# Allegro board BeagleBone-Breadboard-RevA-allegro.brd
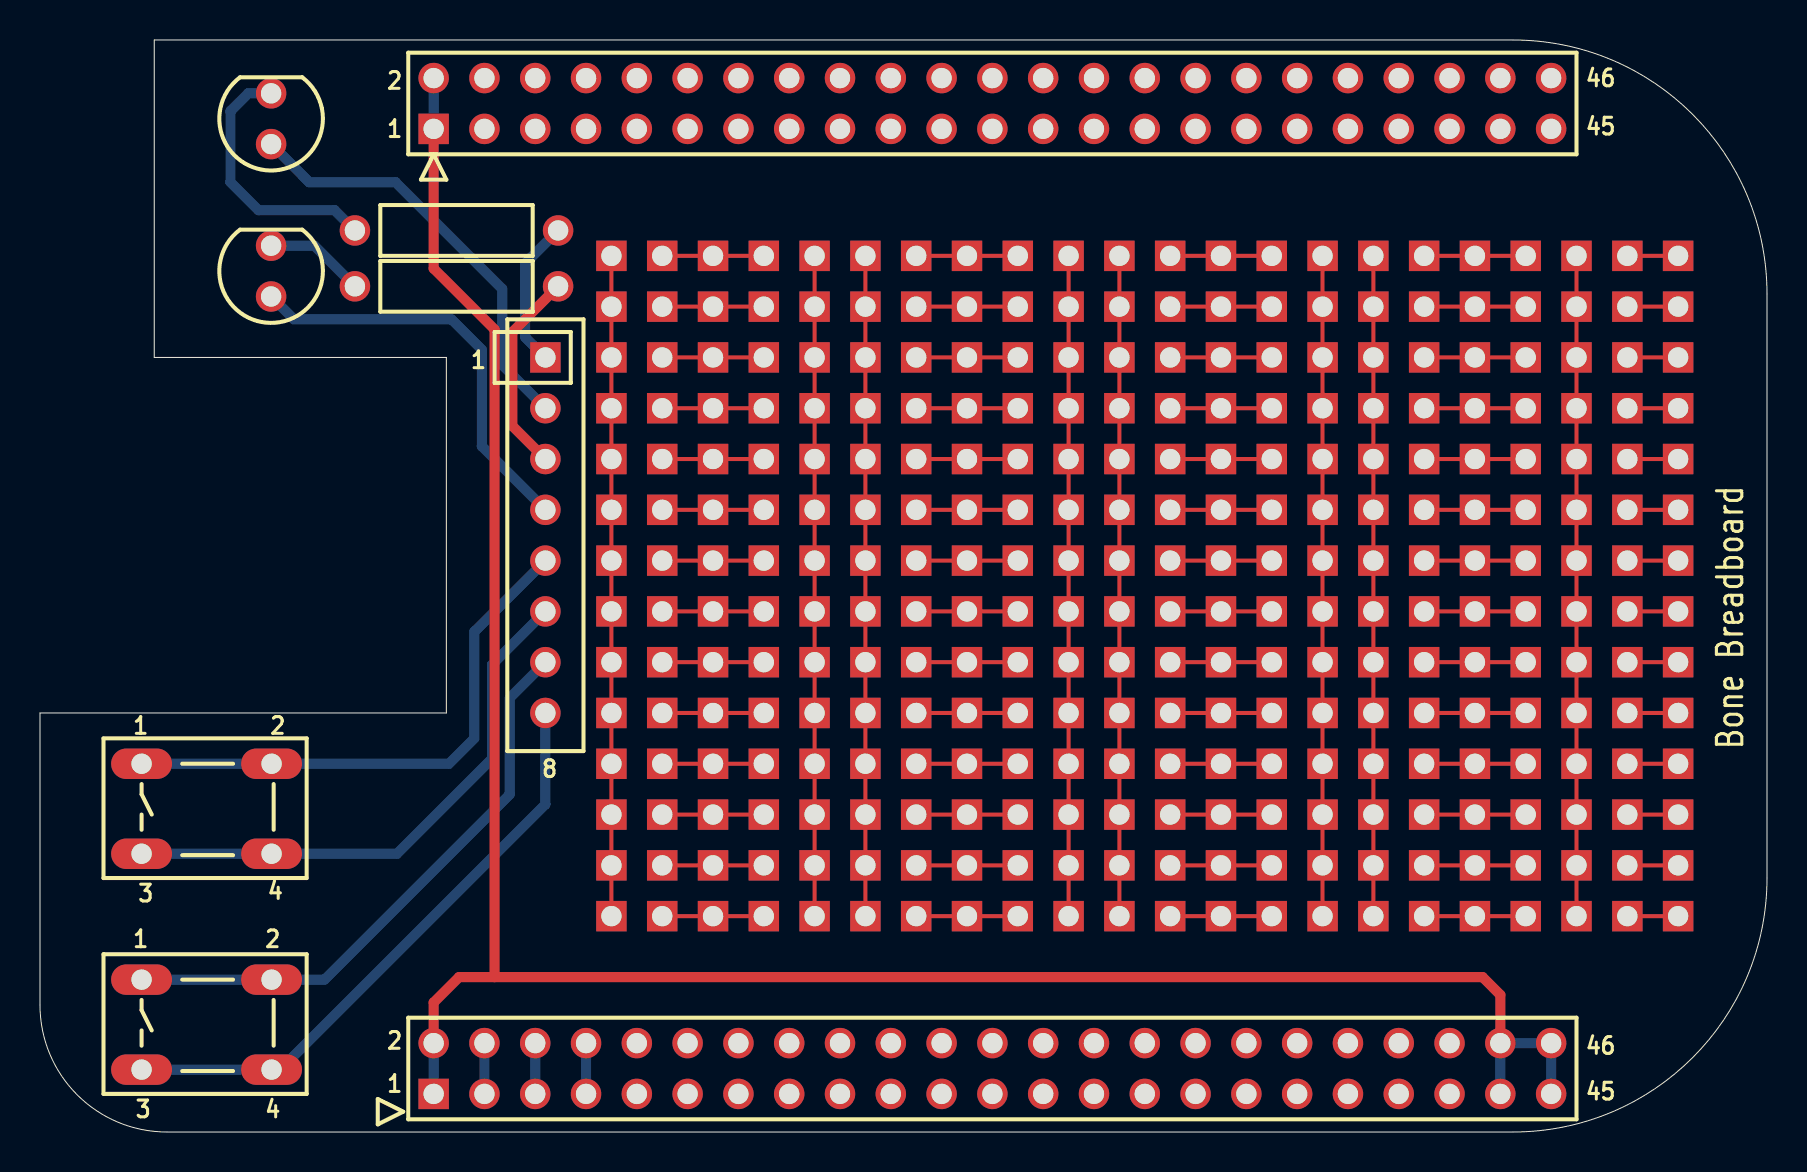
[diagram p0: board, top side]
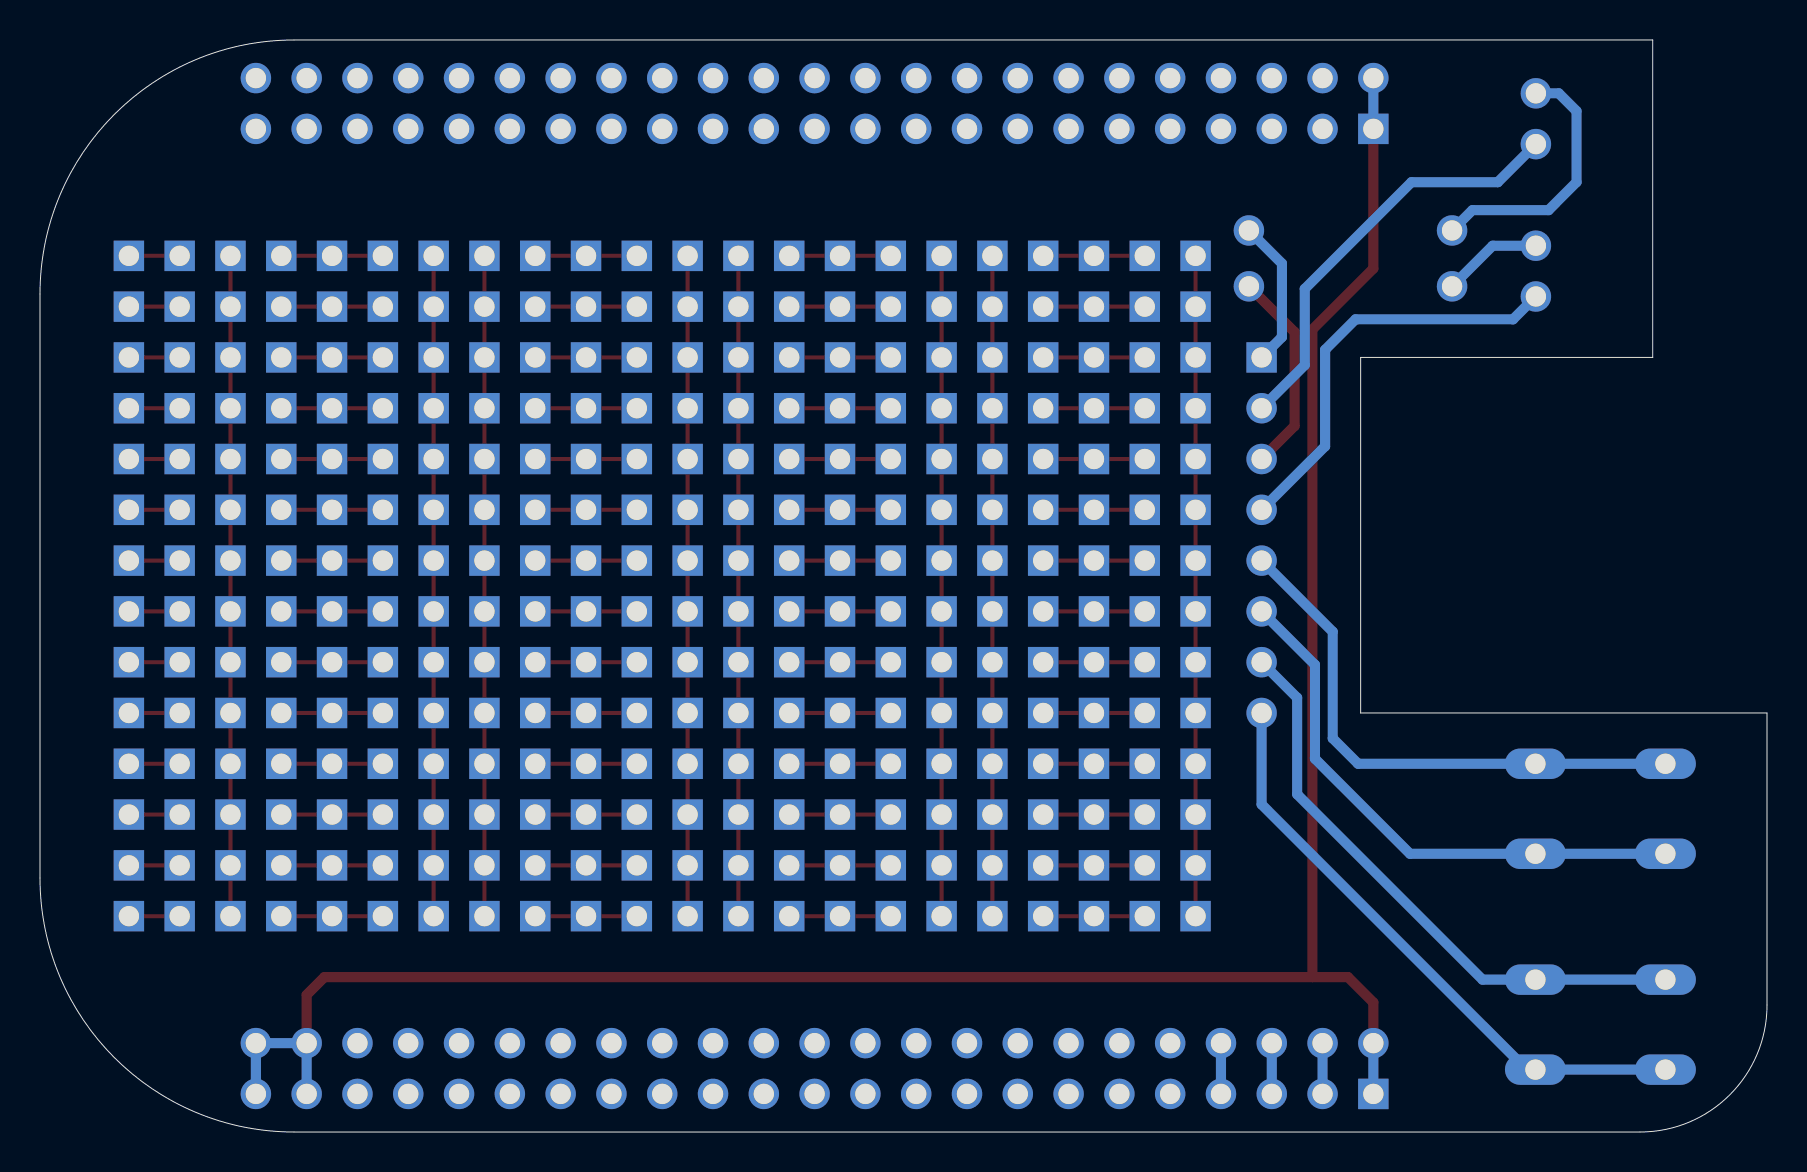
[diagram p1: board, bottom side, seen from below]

Outline 86.36 x 54.61 mm; copper layers: TOP, BOTTOM. Coordinates in mm from the lower left corner of the outline.

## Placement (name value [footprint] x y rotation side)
D1  LED  [LEDS]  11.56 50.67 90 top
D2  LED  [LEDS]  11.56 43.05 90 top
NOREF  -  []  0 0 0 top
NOREF#2  -  []  -358.14 -231.14 0 top
P1  FEMALE HEADER 2x23  [2X23_HDR_FEMALE]  19.68 50.16 180 top
P2  FEMALE HEADER 2x23  [2X23_HDR_FEMALE]  19.68 1.91 180 top
P3  8-PIN HEADER  [8_PIN_HDR_FEMALE]  25.27 38.73 90 top
R1  470  [RESISTOR]  20.83 45.09 180 top
R2  470  [RESISTOR]  20.83 42.29 180 top
S1  SW DIP-2  [BUTTONS]  5.08 18.41 0 top
S2  SW DIP-2  [BUTTONS]  5.08 7.62 0 top
TH1  CONN SOCKET 14x2  [2X14HEADER]  33.66 27.3 0 top
TH2  CONN SOCKET 14x2  [2X14HEADER]  46.35 27.3 0 top
TH3  CONN SOCKET 14x2  [2X14HEADER]  59.05 27.3 0 top
TH4  CONN SOCKET 14x2  [2X14HEADER]  71.75 27.3 0 top
TH5  CONN SOCKET 21x2  [3X14HEADER]  33.66 27.3 0 top
TH6  CONN SOCKET 21x2  [3X14HEADER]  46.35 27.3 0 top
TH7  CONN SOCKET 21x2  [3X14HEADER]  59.05 27.3 0 top
TH8  CONN SOCKET 21x2  [3X14HEADER]  71.75 27.3 0 top
TH9  CONN SOCKET 14  [14HEADER]  79.38 27.3 0 top
TH10  CONN SOCKET 14  [14HEADER]  81.92 27.3 0 top

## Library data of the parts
D1 D2 = LED
P1 P2 = FEMALE HEADER 2x23
P3 = 8-PIN HEADER
R1 R2 = R
S1 S2 = SW DIP-2
TH1-TH4 = CONN SOCKET 14x2
TH5-TH8 = CONN SOCKET 21x2
TH9 TH10 = CONN SOCKET 14

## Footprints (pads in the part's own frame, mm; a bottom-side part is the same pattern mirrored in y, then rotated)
2X14HEADER
  rect 1.524x1.524 hole 1.016: 1(-5.08,16.51) 2(5.08,16.51) 3(-5.08,13.97) 4(5.08,13.97) 5(-5.08,11.43) 6(5.08,11.43) 7(-5.08,8.89) 8(5.08,8.89) 9(-5.08,6.35) 10(5.08,6.35) 11(-5.08,3.81) 12(5.08,3.81) 13(-5.08,1.27) 14(5.08,1.27) 15(-5.08,-1.27) 16(5.08,-1.27) 17(-5.08,-3.81) 18(5.08,-3.81) 19(-5.08,-6.35) 20(5.08,-6.35) 21(-5.08,-8.89) 22(5.08,-8.89) 23(-5.08,-11.43) 24(5.08,-11.43) 25(-5.08,-13.97) 26(5.08,-13.97) 27(-5.08,-16.51) 28(5.08,-16.51)
2X23_HDR_FEMALE
  rect 1.524x1.524 hole 1.016: 1(0,0)
  round 1.524 hole 1.016: 2(0,-2.54) 3(-2.54,0) 4(-2.54,-2.54) 5(-5.08,0) 6(-5.08,-2.54) 7(-7.62,0) 8(-7.62,-2.54) 9(-10.16,0) 10(-10.16,-2.54) 11(-12.7,0) 12(-12.7,-2.54) 13(-15.24,0) 14(-15.24,-2.54) 15(-17.78,0) 16(-17.78,-2.54) 17(-20.32,0) 18(-20.32,-2.54) 19(-22.86,0) 20(-22.86,-2.54) 21(-25.4,0) 22(-25.4,-2.54) 23(-27.94,0) 24(-27.94,-2.54) 25(-30.48,0) 26(-30.48,-2.54) 27(-33.02,0) 28(-33.02,-2.54) 29(-35.56,0) 30(-35.56,-2.54) 31(-38.1,0) 32(-38.1,-2.54) 33(-40.64,0) 34(-40.64,-2.54) 35(-43.18,0) 36(-43.18,-2.54) 37(-45.72,0) 38(-45.72,-2.54) 39(-48.26,0) 40(-48.26,-2.54) 41(-50.8,0) 42(-50.8,-2.54) 43(-53.34,0) 44(-53.34,-2.54) 45(-55.88,0) 46(-55.88,-2.54)
3X14HEADER
  rect 1.524x1.524 hole 1.016: 1(-2.54,16.51) 2(0,16.51) 3(2.54,16.51) 4(-2.54,13.97) 5(0,13.97) 6(2.54,13.97) 7(-2.54,11.43) 8(0,11.43) 9(2.54,11.43) 10(-2.54,8.89) 11(0,8.89) 12(2.54,8.89) 13(-2.54,6.35) 14(0,6.35) 15(2.54,6.35) 16(-2.54,3.81) 17(0,3.81) 18(2.54,3.81) 19(-2.54,1.27) 20(0,1.27) 21(2.54,1.27) 22(-2.54,-1.27) 23(0,-1.27) 24(2.54,-1.27) 25(-2.54,-3.81) 26(0,-3.81) 27(2.54,-3.81) 28(-2.54,-6.35) 29(0,-6.35) 30(2.54,-6.35) 31(-2.54,-8.89) 32(0,-8.89) 33(2.54,-8.89) 34(-2.54,-11.43) 35(0,-11.43) 36(2.54,-11.43) 37(-2.54,-13.97) 38(0,-13.97) 39(2.54,-13.97) 40(-2.54,-16.51) 41(0,-16.51) 42(2.54,-16.51)
8_PIN_HDR_FEMALE
  rect 1.524x1.524 hole 1.016: 1(0,0)
  round 1.524 hole 1.016: 2(-2.54,0) 3(-5.08,0) 4(-7.62,0) 5(-10.16,0) 6(-12.7,0) 7(-15.24,0) 8(-17.78,0)
14HEADER
  rect 1.524x1.524 hole 1.016: 1(0,16.51) 2(0,13.97) 3(0,11.43) 4(0,8.89) 5(0,6.35) 6(0,3.81) 7(0,1.27) 8(0,-1.27) 9(0,-3.81) 10(0,-6.35) 11(0,-8.89) 12(0,-11.43) 13(0,-13.97) 14(0,-16.51)
BUTTONS
  oval 3.048x1.524 hole 1.016: 1(0,0) 2(6.5,0) 3(0,-4.5) 4(6.5,-4.5)
LEDS
  round 1.524 hole 1.016: 1(-1.27,0) 2(1.27,0)
RESISTOR
  round 1.524 hole 1.016: 1(-5.08,0) 2(5.08,0)

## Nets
AGND: P2.34
DGND: P1.1 P1.2 P2.1 P2.2 P2.43 P2.44 P2.45 P2.46
VDD_3V3EXP: P2.3 P2.4
VDD_5V: P2.5 P2.6
VDD_ADC: P2.32
AIN0: P2.39
AIN1: P2.40
AIN2: P2.37
AIN3: P2.38
AIN4: P2.33
AIN5: P2.36
AIN6: P2.35
CLKOUT2: P2.41
EHRPWM1A: P2.14
EHRPWM1B: P2.16
EHRPWM2A: P1.19
EHRPWM2B: P1.13
GPIO0_7: P2.42
GPIO1_0: P1.25
GPIO1_1: P1.24
GPIO1_2: P1.5
GPIO1_3: P1.6
GPIO1_4: P1.23
GPIO1_5: P1.22
GPIO1_6: P1.3
GPIO1_7: P1.4
GPIO1_12: P1.12
GPIO1_13: P1.11
GPIO1_14: P1.16
GPIO1_15: P1.15
GPIO1_26: P1.14
GPIO1_27: P1.17
GPIO1_28: P2.12
GPIO1_29: P1.26
GPIO1_30: P1.21
GPIO1_31: P1.20
GPIO2_1: P1.18
GPIO2_6: P1.45
GPIO2_7: P1.46
GPIO2_8: P1.43
GPIO2_9: P1.44
GPIO2_10: P1.41
GPIO2_11: P1.42
GPIO2_13: P1.40
GPIO2_22: P1.27
GPIO2_23: P1.29
GPIO2_24: P1.28
GPIO2_25: P1.30
GPIO3_19: P2.27
GPIO3_21: P2.25
GPIO_12: P1.39
I2C1_SCL: P2.17
I2C1_SDA: P2.18
I2C2_SCL: P2.19
I2C2_SDA: P2.20
N$40: P1.38
PWR_BUT: P2.9
SPI1_CS0: P2.28
SPI1_D0: P2.29
SPI1_D1: P2.30
SPI1_SCLK: P2.31
SYS_5V: P2.7 P2.8
SYS_RESETN: P2.10
TIMER4: P1.7
TIMER5: P1.9
TIMER6: P1.10
TIMER7: P1.8
UART1_RXD: P2.26
UART1_TXD: P2.24
UART2_RXD: P2.22
UART2_TXD: P2.21
UART3_CTSN: P1.36
UART3_RTSN: P1.34
UART3_RXD: P2.15
UART3_TXD: P2.23
UART4_CTSN: P1.35
UART4_RTSN: P1.33
UART4_RXD: P2.11
UART4_TXD: P2.13
UART5_CTSN: P1.31
UART5_RTSN: P1.32
UART5_TXD: P1.37
N17763164: P3.1 R1.1
N17763549: D1.2(CATHODE) R1.2
N17763744: D1.1(ANODE) P3.2
N17764739: P3.3 R2.1
N17765148: D2.2(CATHODE) R2.2
N17765355: D2.1(ANODE) P3.4
N17766867: P3.5 S1.1(A1) S1.2(A2)
N17767733: P3.6 S1.3(B2) S1.4(B1)
N17770742: P3.8 S2.3(B2) S2.4(B1)
N17770970: P3.7 S2.1(A1) S2.2(A2)
N17781378: TH1.1 TH1.3(2) TH1.5(3) TH1.7(4) TH1.9(5) TH1.11(6) TH1.13(7) TH1.15(8) TH1.17(9) TH1.19(10) TH1.21(11) TH1.23(12) TH1.25(13) TH1.27(14)
N17785215: TH1.2(15) TH1.4(16) TH1.6(17) TH1.8(18) TH1.10(19) TH1.12(20) TH1.14(21) TH1.16(22) TH1.18(23) TH1.20(24) TH1.22(25) TH1.24(26) TH1.26(27) TH1.28
N17790580: TH3.2(15) TH3.4(16) TH3.6(17) TH3.8(18) TH3.10(19) TH3.12(20) TH3.14(21) TH3.16(22) TH3.18(23) TH3.20(24) TH3.22(25) TH3.24(26) TH3.26(27) TH3.28
N17790634: TH3.1 TH3.3(2) TH3.5(3) TH3.7(4) TH3.9(5) TH3.11(6) TH3.13(7) TH3.15(8) TH3.17(9) TH3.19(10) TH3.21(11) TH3.23(12) TH3.25(13) TH3.27(14)
N17791201: TH2.2(15) TH2.4(16) TH2.6(17) TH2.8(18) TH2.10(19) TH2.12(20) TH2.14(21) TH2.16(22) TH2.18(23) TH2.20(24) TH2.22(25) TH2.24(26) TH2.26(27) TH2.28
N17791255: TH2.1 TH2.3(2) TH2.5(3) TH2.7(4) TH2.9(5) TH2.11(6) TH2.13(7) TH2.15(8) TH2.17(9) TH2.19(10) TH2.21(11) TH2.23(12) TH2.25(13) TH2.27(14)
N17791878: TH4.2(15) TH4.4(16) TH4.6(17) TH4.8(18) TH4.10(19) TH4.12(20) TH4.14(21) TH4.16(22) TH4.18(23) TH4.20(24) TH4.22(25) TH4.24(26) TH4.26(27) TH4.28
N17791932: TH4.1 TH4.3(2) TH4.5(3) TH4.7(4) TH4.9(5) TH4.11(6) TH4.13(7) TH4.15(8) TH4.17(9) TH4.19(10) TH4.21(11) TH4.23(12) TH4.25(13) TH4.27(14)
N17792911: TH5.1 TH5.2 TH5.3
N17794334: TH5.4 TH5.5 TH5.6
N17794834: TH5.7 TH5.8 TH5.9
N17795340: TH5.10 TH5.11 TH5.12
N17795852: TH5.13 TH5.14 TH5.15
N17796370: TH5.16 TH5.17 TH5.18
N17796894: TH5.19 TH5.20 TH5.21
N17797408: TH5.40 TH5.41 TH5.42
N17798957: TH5.37 TH5.38 TH5.39
N17799499: TH5.34 TH5.35 TH5.36
N17802057: TH5.31 TH5.32 TH5.33
N17802061: TH5.28 TH5.29 TH5.30
N17802071: TH5.25 TH5.26 TH5.27
N17803192: TH5.22 TH5.23 TH5.24
N17803960: TH6.40 TH6.41 TH6.42
N17803964: TH6.37 TH6.38 TH6.39
N17803974: TH6.34 TH6.35 TH6.36
N17803984: TH6.31 TH6.32 TH6.33
N17803988: TH6.28 TH6.29 TH6.30
N17803998: TH6.25 TH6.26 TH6.27
N17804014: TH6.22 TH6.23 TH6.24
N17804024: TH6.1 TH6.2 TH6.3
N17804034: TH6.4 TH6.5 TH6.6
N17804044: TH6.7 TH6.8 TH6.9
N17804054: TH6.10 TH6.11 TH6.12
N17804064: TH6.13 TH6.14 TH6.15
N17804074: TH6.16 TH6.17 TH6.18
N17804084: TH6.19 TH6.20 TH6.21
N17804942: TH7.40 TH7.41 TH7.42
N17804946: TH7.37 TH7.38 TH7.39
N17804956: TH7.34 TH7.35 TH7.36
N17804966: TH7.31 TH7.32 TH7.33
N17804970: TH7.28 TH7.29 TH7.30
N17804980: TH7.25 TH7.26 TH7.27
N17804996: TH7.22 TH7.23 TH7.24
N17805006: TH7.1 TH7.2 TH7.3
N17805016: TH7.4 TH7.5 TH7.6
N17805026: TH7.7 TH7.8 TH7.9
N17805036: TH7.10 TH7.11 TH7.12
N17805046: TH7.13 TH7.14 TH7.15
N17805056: TH7.16 TH7.17 TH7.18
N17805066: TH7.19 TH7.20 TH7.21
N17806008: TH8.40 TH8.41 TH8.42
N17806012: TH8.37 TH8.38 TH8.39
N17806022: TH8.34 TH8.35 TH8.36
N17806032: TH8.31 TH8.32 TH8.33
N17806036: TH8.28 TH8.29 TH8.30
N17806046: TH8.25 TH8.26 TH8.27
N17806062: TH8.22 TH8.23 TH8.24
N17806072: TH8.1 TH8.2 TH8.3
N17806082: TH8.4 TH8.5 TH8.6
N17806092: TH8.7 TH8.8 TH8.9
N17806102: TH8.10 TH8.11 TH8.12
N17806112: TH8.13 TH8.14 TH8.15
N17806122: TH8.16 TH8.17 TH8.18
N17806132: TH8.19 TH8.20 TH8.21
N18045051: TH9.1 TH10.1
N18045848: TH9.2 TH10.2
N18047612: TH9.3 TH10.3
N18051781: TH9.4 TH10.4
N18052584: TH9.5 TH10.5
N18053389: TH9.6 TH10.6
N18054196: TH9.7 TH10.7
N18055005: TH9.8 TH10.8
N18055816: TH9.9 TH10.9
N18056629: TH9.10 TH10.10
N18057444: TH9.11 TH10.11
N18058261: TH9.12 TH10.12
N18059080: TH9.13 TH10.13
N18059901: TH9.14 TH10.14

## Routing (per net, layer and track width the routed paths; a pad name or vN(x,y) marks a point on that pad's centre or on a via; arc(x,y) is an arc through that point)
DGND: length 115.1
  TOP w0.508: 22.73,7.75 20.95,7.75 19.68,6.48 P2.2 ; 22.73,7.75 22.73,40.13 19.68,43.18 P1.1 ; 22.73,7.75 72.14,7.75 73.03,6.86 P2.44
  BOTTOM w0.508: P1.2 P1.1 ; P2.1 P2.2 ; P2.45 P2.46 P2.44 P2.43
VDD_3V3EXP: length 2.5
  BOTTOM w0.508: P2.4 P2.3
VDD_5V: length 2.5
  BOTTOM w0.508: P2.6 P2.5
SYS_5V: length 2.5
  BOTTOM w0.508: P2.8 P2.7
N17763164: length 7.5
  BOTTOM w0.508: R1.1 24.26,43.43 24.26,39.75 P3.1
N17763549: length 13.2
  BOTTOM w0.508: R1.2 14.73,46.1 10.92,46.1 9.53,47.5 9.53,51.05 10.41,51.94 D1.2
N17763744: length 21.4
  BOTTOM w0.508: D1.1 13.46,47.5 17.78,47.5 23.11,42.16 23.11,38.35 P3.2
N17764739: length 10.3
  TOP w0.508: P3.3 23.62,35.31 23.62,40.01 R2.1
N17765148: length 5
  BOTTOM w0.508: D2.2 13.72,44.32 R2.2
N17765355: length 21
  BOTTOM w0.508: 11.56,41.78 12.7,40.64 20.57,40.64 22.1,39.12 22.1,34.29 P3.4
N17766867: length 27.5
  BOTTOM w0.508: P3.5 21.72,25.02 21.72,19.68 20.45,18.41 S1.2 S1.1
N17767733: length 28
  BOTTOM w0.508: S1.3 S1.4 17.85,13.91 22.61,18.67 22.61,23.37 P3.6
N17770742: length 30.3
  BOTTOM w0.508: S2.3 S2.4 12.01,3.12 25.27,16.38 P3.8
N17770970: length 29.6
  BOTTOM w0.508: S2.1 S2.2 14.22,7.62 23.5,16.89 23.5,21.72 25.27,23.5
N17781378: length 33
  TOP w0.203: 28.57,10.79 TH1.23 TH1.21 TH1.19 TH1.17 TH1.15 TH1.13 TH1.11 TH1.9 TH1.7 TH1.5 TH1.3 TH1.1
N17785215: length 33
  TOP w0.203: 38.73,10.79 TH1.24 TH1.22 TH1.20 TH1.18 TH1.16 TH1.14 TH1.12 TH1.10 TH1.8 TH1.6 TH1.4 TH1.2
N17790580: length 33
  TOP w0.203: TH3.2 TH3.4 TH3.6 TH3.8 TH3.10 TH3.12 TH3.14 TH3.16 TH3.18 TH3.20 TH3.22 TH3.24 64.14,10.79
N17790634: length 33
  TOP w0.203: 53.98,10.79 TH3.23 TH3.21 TH3.19 TH3.17 TH3.15 TH3.13 TH3.11 TH3.9 TH3.7 TH3.5 TH3.3 TH3.1
N17791201: length 33
  TOP w0.203: 51.44,43.81 51.44,10.79
N17791255: length 33
  TOP w0.203: 41.27,10.79 TH2.23 TH2.21 TH2.19 TH2.17 TH2.15 TH2.13 TH2.11 TH2.9 TH2.7 TH2.5 TH2.3 TH2.1
N17791878: length 33
  TOP w0.203: TH4.2 TH4.4 TH4.6 TH4.8 TH4.10 TH4.12 TH4.14 TH4.16 TH4.18 TH4.20 TH4.22 TH4.24 76.83,10.79
N17791932: length 33
  TOP w0.203: TH4.1 TH4.3 TH4.5 TH4.7 TH4.9 TH4.11 TH4.13 TH4.15 TH4.17 TH4.19 TH4.21 TH4.23 66.67,10.79
N17792911: length 5.1
  TOP w0.203: TH5.1 TH5.2 TH5.3
N17794334: length 5.1
  TOP w0.203: TH5.6 TH5.5 TH5.4
N17794834: length 5.1
  TOP w0.203: TH5.7 TH5.8 TH5.9
N17795340: length 5.1
  TOP w0.203: TH5.12 TH5.11 TH5.10
N17795852: length 5.1
  TOP w0.203: TH5.13 TH5.14 TH5.15
N17796370: length 5.1
  TOP w0.203: TH5.16 TH5.17 TH5.18
N17796894: length 5.1
  TOP w0.203: TH5.21 TH5.20 TH5.19
N17797408: length 5.1
  TOP w0.203: 36.2,10.79 31.11,10.79
N17798957: length 5.1
  TOP w0.203: 36.2,13.34 31.11,13.34
N17799499: length 5.1
  TOP w0.203: TH5.34 TH5.35 TH5.36
N17802057: length 5.1
  TOP w0.203: TH5.31 TH5.32 TH5.33
N17802061: length 5.1
  TOP w0.203: TH5.30 TH5.29 TH5.28
N17802071: length 5.1
  TOP w0.203: TH5.25 TH5.26 TH5.27
N17803192: length 5.1
  TOP w0.203: TH5.22 TH5.23 TH5.24
N17803960: length 5.1
  TOP w0.203: 48.9,10.79 43.81,10.79
N17803964: length 5.1
  TOP w0.203: 48.9,13.34 43.81,13.34
N17803974: length 5.1
  TOP w0.203: 48.9,15.88 TH6.35 TH6.34
N17803984: length 5.1
  TOP w0.203: TH6.31 TH6.32 48.9,18.41
N17803988: length 5.1
  TOP w0.203: TH6.28 TH6.29 48.9,20.95
N17803998: length 5.1
  TOP w0.203: 48.9,23.5 TH6.26 TH6.25
N17804014: length 5.1
  TOP w0.203: TH6.22 TH6.23 48.9,26.04
N17804024: length 5.1
  TOP w0.203: TH6.1 TH6.2 48.9,43.81
N17804034: length 5.1
  TOP w0.203: TH6.4 TH6.5 48.9,41.27
N17804044: length 5.1
  TOP w0.203: 48.9,38.73 TH6.8 TH6.7
N17804054: length 5.1
  TOP w0.203: 48.9,36.2 TH6.11 TH6.10
N17804064: length 5.1
  TOP w0.203: 48.9,33.66 TH6.14 TH6.13
N17804074: length 5.1
  TOP w0.203: TH6.16 TH6.17 48.9,31.11
N17804084: length 5.1
  TOP w0.203: 48.9,28.57 TH6.20 TH6.19
N17804942: length 5.1
  TOP w0.203: 61.59,10.79 56.52,10.79
N17804946: length 5.1
  TOP w0.203: 61.59,13.34 56.52,13.34
N17804956: length 5.1
  TOP w0.203: TH7.34 TH7.35 TH7.36
N17804966: length 5.1
  TOP w0.203: TH7.31 TH7.32 TH7.33
N17804970: length 5.1
  TOP w0.203: TH7.28 TH7.29 TH7.30
N17804980: length 5.1
  TOP w0.203: TH7.25 TH7.26 TH7.27
N17804996: length 5.1
  TOP w0.203: TH7.24 TH7.23 TH7.22
N17805006: length 5.1
  TOP w0.203: TH7.3 TH7.2 TH7.1
N17805016: length 5.1
  TOP w0.203: TH7.6 TH7.5 TH7.4
N17805026: length 5.1
  TOP w0.203: TH7.7 TH7.8 TH7.9
N17805036: length 5.1
  TOP w0.203: TH7.12 TH7.11 TH7.10
N17805046: length 5.1
  TOP w0.203: TH7.15 TH7.14 TH7.13
N17805056: length 5.1
  TOP w0.203: TH7.18 TH7.17 TH7.16
N17805066: length 5.1
  TOP w0.203: TH7.19 TH7.20 TH7.21
N17806008: length 5.1
  TOP w0.203: 74.3,10.79 69.22,10.79
N17806012: length 5.1
  TOP w0.203: 74.3,13.34 69.22,13.34
N17806022: length 5.1
  TOP w0.203: TH8.36 TH8.35 69.22,15.88
N17806032: length 5.1
  TOP w0.203: TH8.33 TH8.32 69.22,18.41
N17806036: length 5.1
  TOP w0.203: TH8.30 TH8.29 69.22,20.95
N17806046: length 5.1
  TOP w0.203: 69.22,23.5 TH8.26 TH8.27
N17806062: length 5.1
  TOP w0.203: 69.22,26.04 TH8.23 TH8.24
N17806072: length 5.1
  TOP w0.203: TH8.3 TH8.2 69.22,43.81
N17806082: length 5.1
  TOP w0.203: 69.22,41.27 TH8.5 TH8.6
N17806092: length 5.1
  TOP w0.203: TH8.9 TH8.8 69.22,38.73
N17806102: length 5.1
  TOP w0.203: TH8.12 TH8.11 69.22,36.2
N17806112: length 5.1
  TOP w0.203: 69.22,33.66 TH8.14 TH8.15
N17806122: length 5.1
  TOP w0.203: 69.22,31.11 TH8.17 TH8.18
N17806132: length 5.1
  TOP w0.203: TH8.21 TH8.20 69.22,28.57
N18045051: length 2.5
  TOP w0.203: TH9.1 TH10.1
N18045848: length 2.5
  TOP w0.203: TH9.2 TH10.2
N18047612: length 2.5
  TOP w0.203: TH9.3 TH10.3
N18051781: length 2.5
  TOP w0.203: TH9.4 TH10.4
N18052584: length 2.5
  TOP w0.203: TH9.5 TH10.5
N18053389: length 2.5
  TOP w0.203: TH9.6 TH10.6
N18054196: length 2.5
  TOP w0.203: TH9.7 TH10.7
N18055005: length 2.5
  TOP w0.203: TH9.8 TH10.8
N18055816: length 2.5
  TOP w0.203: TH9.9 TH10.9
N18056629: length 2.5
  TOP w0.203: TH9.10 TH10.10
N18057444: length 2.5
  TOP w0.203: TH9.11 TH10.11
N18058261: length 2.5
  TOP w0.203: TH9.12 TH10.12
N18059080: length 2.5
  TOP w0.203: 79.38,13.34 81.92,13.34
N18059901: length 2.5
  TOP w0.203: 79.38,10.79 81.92,10.79

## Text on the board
User.Comments: EMAIL: info@pcbvn.com | WEBSITE : www.pcbvn.com | MOBILE : +84908222784 | nampth@yahoo.com | DATE: | CIRCUITCO ELECTRONICS | 03/11/2011 | BONE BREADBOARD | PCB VIET NAM
Ref Des/Silkscreen Top: Bone Breadboard
PAGE_OUTLINE: FAB | LAYER SCHEDULE | SCALE: NONE | SMASK_TOP | SMASK_BOT | SILK_TOP | LAYER 1 | LAYER 2 | BONE BREADBOARD | CIRCUITCO ELECTRONICS
DIMENSION: ASSY_TOP
ASSY_BOT: ASSY_BOT
LAYER1_TOP: LAYER1_TOP
User.5: LAYER2_BOT
User.6: PMASK_TOP
User.7: PMASK_BOT
User.8: SMASK_TOP
User.9: SMASK_BOT
User.10: SILK_TOP
User.11: SILK_BOT
User.12: S2 | S1 | D2 | D1 | R2 | R1 | P3 | P1 | P2
User.13: FIGURE | SIZE | 40.0 | DRILL CHART: TOP to BOTTOM | ALL UNITS ARE IN MILS | PLATED | QTY | 8 | 416
